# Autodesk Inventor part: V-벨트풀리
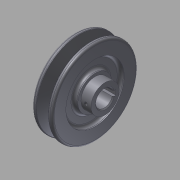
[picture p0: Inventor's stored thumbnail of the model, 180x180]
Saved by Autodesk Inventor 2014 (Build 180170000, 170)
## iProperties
Company: 한국ATC센터
Created: 2014-07
Part Number: V-벨트풀리
Document SubType Name: Modeling
Designer: KYOUNG IL JANG
Density: 7.87 g/cm^3
Material: 강철, 탄소
Mass: 593.766 g
Surface Area: 234.121 cm^2
Volume: 75.4468 cm^3
Appearance: 강철
Author: KYOUNG IL JANG
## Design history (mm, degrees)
sketch "스케치1"
  geometry: L1 (-15, 0)-(15, 0); L2 (-15, 0)-(-15, 17); L3 (-15, 17)-(-11, 17); L4 (-11, 17)-(-11, 29); L5 (-11, 29)-(-15, 29); L6 (-15, 29)-(-15, 42.5); L7 (-15, 42.5)-(-10.976, 42.5); L8 (-10.976, 42.5)-(-7.154, 30); L9 (-7.154, 30)-(-2.846, 30); L10 (-2.846, 30)-(0.976, 42.5); L11 (0.976, 42.5)-(5, 42.5); L12 (5, 42.5)-(5, 29); L13 (5, 29)-(1, 29); L14 (1, 29)-(1, 17); L15 (1, 17)-(5, 17); L16 (5, 17)-(5, 14); L17 (5, 14)-(15, 14); L18 (15, 14)-(15, 0); L19 (-9.6, 38)-(-0.4, 38); 2 further points
  constraints: 38 end point, 11 parallel, 7 collinear, 3 equal length, 3 perpendicular, 2 point on line, 1 coincident, 1 horizontal, 1 midpoint
  dimensions: "d0" = 30 distance of L1.start L1.end; "d1" = 4.5 distance between parallel lines of L7 L19; "d2" = 8 distance between parallel lines of L9 L19; "d3" = 9.2 distance of L19.start L19.end; "d4" = 34 deg angle of L10 L8; "d5" = 20 distance between parallel lines of L12 L6; "d6" = 76 diameter of L19 L1; "d7" = 4 distance of L2.end L3.end; "d8" = 34 diameter of L3 L1; "d9" = 58 diameter of L5 L1; "d10" = 28 diameter of L17 L1
revolve "회전1" sketch "스케치1" stored, may be unused: angle "d11" = 90 deg
sketch "스케치2"
  geometry: L1 (-2.5, 8.124)-(-2.5, 10.8); L2 (-2.5, 10.8)-(2.5, 10.8); L3 (2.5, 10.8)-(2.5, 8.124); A1 r 8.5 centre (0, 0) between (-2.5, 8.124) and (2.5, 8.124); 1 further point
  constraints: 6 end point, 2 parallel, 2 point on circle, 1 centre point, 1 coincident, 1 horizontal, 1 vertical
  dimensions: "d12" = 17 diameter of A1; "d13" = 5 distance of L1.end L2.end; "d14" = 19.3 dimension on A1 L2 (computed from d12)
extrude "돌출1" cut sketch "스케치2" stored distance "d15" = 10; taper "d16" = 0 deg
chamfer "모따기1" distance "d17" = 1; stored, may be unused: second distance "d18" = 2, angle "d19" = 45 deg
node "작업 평면1"
sketch "스케치3"
  geometry: L1 (5, -14)-(5, 14) reference; 3 further points
  constraints: 1 horizontal alignment, 1 midpoint
  dimensions: "d20" = 5 distance from line of L1 point (0, 0)
hole "구멍1" sketch "스케치3" at (0, 0) diameter "d21" = 3.242; stored, may be unused: countersink angle "d25" = 90 deg, drill point angle "d27" = 118 deg; dims "d22" = 6, "d23" = 4, "d24" = 2, "d26" = 8
fillet "모깎기1" dims "d28" = 3, "d29" = 2, "d30" = 0.5, "d31" = 1
node "솔리드1"
